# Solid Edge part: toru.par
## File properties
Author: Romil
Template: iso part.par
Last saved by: Romil
Revision: 7
Application: Solid Edge
Accuracy: 0.990
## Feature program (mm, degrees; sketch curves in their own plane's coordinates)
lofted protrusion "unnamed LoftedProtrusion 1"
lofted protrusion "unnamed LoftedProtrusion 2"
lofted protrusion "unnamed LoftedProtrusion 3"
lofted protrusion "unnamed LoftedProtrusion 4"
lofted protrusion "unnamed LoftedProtrusion 5"
lofted protrusion "unnamed LoftedProtrusion 6"
lofted protrusion "unnamed LoftedProtrusion 7"
lofted protrusion "unnamed LoftedProtrusion 8"
lofted protrusion "unnamed LoftedProtrusion 9"
lofted protrusion "unnamed LoftedProtrusion 10"
lofted protrusion "unnamed LoftedProtrusion 11"
lofted protrusion "unnamed LoftedProtrusion 12"
lofted protrusion "unnamed LoftedProtrusion 13"
lofted protrusion "unnamed LoftedProtrusion 14"
lofted protrusion "unnamed LoftedProtrusion 15"
lofted protrusion "unnamed LoftedProtrusion 16"
lofted protrusion "unnamed LoftedProtrusion 17"
lofted protrusion "unnamed LoftedProtrusion 18"
lofted protrusion "unnamed LoftedProtrusion 19"
lofted protrusion "unnamed LoftedProtrusion 20"
lofted protrusion "unnamed LoftedProtrusion 21"
lofted protrusion "unnamed LoftedProtrusion 22"
lofted protrusion "unnamed LoftedProtrusion 23"
lofted protrusion "unnamed LoftedProtrusion 24"
lofted protrusion "unnamed LoftedProtrusion 25"
lofted protrusion "unnamed LoftedProtrusion 26"
lofted protrusion "unnamed LoftedProtrusion 27"
lofted protrusion "unnamed LoftedProtrusion 28"
lofted protrusion "unnamed LoftedProtrusion 29"
lofted protrusion "unnamed LoftedProtrusion 30"
lofted protrusion "unnamed LoftedProtrusion 31"
lofted protrusion "unnamed LoftedProtrusion 32"
lofted protrusion "unnamed LoftedProtrusion 33"
lofted protrusion "unnamed LoftedProtrusion 34"
lofted protrusion "unnamed LoftedProtrusion 35"
lofted protrusion "unnamed LoftedProtrusion 36"
lofted protrusion "unnamed LoftedProtrusion 37"
lofted protrusion "unnamed LoftedProtrusion 38"
lofted protrusion "unnamed LoftedProtrusion 39"
lofted protrusion "unnamed LoftedProtrusion 40"
lofted protrusion "unnamed LoftedProtrusion 41"
lofted protrusion "unnamed LoftedProtrusion 42"
lofted protrusion "unnamed LoftedProtrusion 43"
lofted protrusion "unnamed LoftedProtrusion 44"
lofted protrusion "unnamed LoftedProtrusion 45"
lofted protrusion "unnamed LoftedProtrusion 46"
lofted protrusion "unnamed LoftedProtrusion 47"
lofted protrusion "unnamed LoftedProtrusion 48"
lofted protrusion "unnamed LoftedProtrusion 49"
lofted protrusion "unnamed LoftedProtrusion 50"
lofted protrusion "unnamed LoftedProtrusion 51"
lofted protrusion "unnamed LoftedProtrusion 52"
lofted protrusion "unnamed LoftedProtrusion 53"
lofted protrusion "unnamed LoftedProtrusion 54"
lofted protrusion "unnamed LoftedProtrusion 55"
lofted protrusion "unnamed LoftedProtrusion 56"
lofted protrusion "unnamed LoftedProtrusion 57"
lofted protrusion "unnamed LoftedProtrusion 58"
lofted protrusion "unnamed LoftedProtrusion 59"
lofted protrusion "unnamed LoftedProtrusion 60"
lofted protrusion "unnamed LoftedProtrusion 61"
lofted protrusion "unnamed LoftedProtrusion 62"
lofted protrusion "unnamed LoftedProtrusion 63"
lofted protrusion "unnamed LoftedProtrusion 64"
lofted protrusion "unnamed LoftedProtrusion 65"
lofted protrusion "unnamed LoftedProtrusion 66"
lofted protrusion "unnamed LoftedProtrusion 67"
lofted protrusion "unnamed LoftedProtrusion 68"
lofted protrusion "unnamed LoftedProtrusion 69"
lofted protrusion "unnamed LoftedProtrusion 70"
lofted protrusion "unnamed LoftedProtrusion 71"
lofted protrusion "unnamed LoftedProtrusion 72"
lofted protrusion "unnamed LoftedProtrusion 73"
lofted protrusion "unnamed LoftedProtrusion 74"
lofted protrusion "unnamed LoftedProtrusion 75"
lofted protrusion "unnamed LoftedProtrusion 76"
lofted protrusion "unnamed LoftedProtrusion 77"
lofted protrusion "unnamed LoftedProtrusion 78"
lofted protrusion "unnamed LoftedProtrusion 79"
lofted protrusion "unnamed LoftedProtrusion 80"
lofted protrusion "unnamed LoftedProtrusion 81"
lofted protrusion "unnamed LoftedProtrusion 82"
lofted protrusion "unnamed LoftedProtrusion 83"
lofted protrusion "unnamed LoftedProtrusion 84"
lofted protrusion "unnamed LoftedProtrusion 85"
lofted protrusion "unnamed LoftedProtrusion 86"
lofted protrusion "unnamed LoftedProtrusion 87"
lofted protrusion "unnamed LoftedProtrusion 88"
lofted protrusion "unnamed LoftedProtrusion 89"
lofted protrusion "unnamed LoftedProtrusion 90"
lofted protrusion "unnamed LoftedProtrusion 91"
lofted protrusion "unnamed LoftedProtrusion 92"
lofted protrusion "unnamed LoftedProtrusion 93"
lofted protrusion "unnamed LoftedProtrusion 94"
lofted protrusion "unnamed LoftedProtrusion 95"
lofted protrusion "unnamed LoftedProtrusion 96"
lofted protrusion "unnamed LoftedProtrusion 97"
lofted protrusion "unnamed LoftedProtrusion 98"
lofted protrusion "unnamed LoftedProtrusion 99"
lofted protrusion "unnamed LoftedProtrusion 100"
lofted protrusion "unnamed LoftedProtrusion 101"
lofted protrusion "unnamed LoftedProtrusion 102"
lofted protrusion "unnamed LoftedProtrusion 103"
lofted protrusion "unnamed LoftedProtrusion 104"
lofted protrusion "unnamed LoftedProtrusion 105"
lofted protrusion "unnamed LoftedProtrusion 106"
lofted protrusion "unnamed LoftedProtrusion 107"
lofted protrusion "unnamed LoftedProtrusion 108"
lofted protrusion "unnamed LoftedProtrusion 109"
lofted protrusion "unnamed LoftedProtrusion 110"
lofted protrusion "unnamed LoftedProtrusion 111"
lofted protrusion "unnamed LoftedProtrusion 112"
lofted protrusion "unnamed LoftedProtrusion 113"
lofted protrusion "unnamed LoftedProtrusion 114"
lofted protrusion "unnamed LoftedProtrusion 115"
lofted protrusion "unnamed LoftedProtrusion 116"
lofted protrusion "unnamed LoftedProtrusion 117"
lofted protrusion "unnamed LoftedProtrusion 118"
lofted protrusion "unnamed LoftedProtrusion 119"
lofted protrusion "unnamed LoftedProtrusion 120"
lofted protrusion "unnamed LoftedProtrusion 121"
lofted protrusion "unnamed LoftedProtrusion 122"
lofted protrusion "unnamed LoftedProtrusion 123"
lofted protrusion "unnamed LoftedProtrusion 124"
lofted protrusion "unnamed LoftedProtrusion 125"
lofted protrusion "unnamed LoftedProtrusion 126"
lofted protrusion "unnamed LoftedProtrusion 127"
lofted protrusion "unnamed LoftedProtrusion 128"
lofted protrusion "unnamed LoftedProtrusion 129"
lofted protrusion "unnamed LoftedProtrusion 130"
lofted protrusion "unnamed LoftedProtrusion 131"
lofted protrusion "unnamed LoftedProtrusion 132"
lofted protrusion "unnamed LoftedProtrusion 133"
lofted protrusion "unnamed LoftedProtrusion 134"
lofted protrusion "unnamed LoftedProtrusion 135"
lofted protrusion "unnamed LoftedProtrusion 136"
lofted protrusion "unnamed LoftedProtrusion 137"
lofted protrusion "unnamed LoftedProtrusion 138"
lofted protrusion "unnamed LoftedProtrusion 139"
lofted protrusion "unnamed LoftedProtrusion 140"
lofted protrusion "unnamed LoftedProtrusion 141"
lofted protrusion "unnamed LoftedProtrusion 142"
lofted protrusion "unnamed LoftedProtrusion 143"
lofted protrusion "unnamed LoftedProtrusion 144"
lofted protrusion "unnamed LoftedProtrusion 145"
lofted protrusion "unnamed LoftedProtrusion 146"
lofted protrusion "unnamed LoftedProtrusion 147"
lofted protrusion "unnamed LoftedProtrusion 148"
lofted protrusion "unnamed LoftedProtrusion 149"
lofted protrusion "unnamed LoftedProtrusion 150"
lofted protrusion "unnamed LoftedProtrusion 151"
lofted protrusion "unnamed LoftedProtrusion 152"
lofted protrusion "unnamed LoftedProtrusion 153"
lofted protrusion "unnamed LoftedProtrusion 154"
lofted protrusion "unnamed LoftedProtrusion 155"
lofted protrusion "unnamed LoftedProtrusion 156"
lofted protrusion "unnamed LoftedProtrusion 157"
lofted protrusion "unnamed LoftedProtrusion 158"
lofted protrusion "unnamed LoftedProtrusion 159"
lofted protrusion "unnamed LoftedProtrusion 160"
lofted protrusion "unnamed LoftedProtrusion 161"
lofted protrusion "unnamed LoftedProtrusion 162"
lofted protrusion "unnamed LoftedProtrusion 163"
lofted protrusion "unnamed LoftedProtrusion 164"
lofted protrusion "unnamed LoftedProtrusion 165"
lofted protrusion "unnamed LoftedProtrusion 166"
lofted protrusion "unnamed LoftedProtrusion 167"
lofted protrusion "unnamed LoftedProtrusion 168"
lofted protrusion "unnamed LoftedProtrusion 169"
fillet "Round_1" radius 0.2
fillet "unnamed Round 1"
fillet "unnamed Round 2"
fillet "unnamed Round 3"
fillet "unnamed Round 4"
fillet "unnamed Round 5"
fillet "unnamed Round 6"
fillet "unnamed Round 7"
fillet "unnamed Round 8"
fillet "unnamed Round 9"
fillet "unnamed Round 10"
fillet "unnamed Round 11"
fillet "unnamed Round 12"
fillet "unnamed Round 13"
fillet "unnamed Round 14"
fillet "unnamed Round 15"
fillet "unnamed Round 16"
fillet "unnamed Round 17"
fillet "unnamed Round 18"
fillet "unnamed Round 19"
fillet "unnamed Round 20"
fillet "unnamed Round 21"
fillet "unnamed Round 22"
fillet "unnamed Round 23"
fillet "unnamed Round 24"
fillet "unnamed Round 25"
fillet "unnamed Round 26"
fillet "unnamed Round 27"
fillet "unnamed Round 28"
fillet "unnamed Round 29"
fillet "unnamed Round 30"
fillet "unnamed Round 31"
fillet "unnamed Round 32"
fillet "unnamed Round 33"
fillet "unnamed Round 34"
fillet "unnamed Round 35"
fillet "unnamed Round 36"
fillet "unnamed Round 37"
fillet "unnamed Round 38"
fillet "unnamed Round 39"
fillet "unnamed Round 40"
fillet "unnamed Round 41"
fillet "unnamed Round 42"
fillet "unnamed Round 43"
fillet "unnamed Round 44"
fillet "unnamed Round 45"
fillet "unnamed Round 46"
fillet "unnamed Round 47"
fillet "unnamed Round 48"
fillet "unnamed Round 49"
fillet "unnamed Round 50"
fillet "unnamed Round 51"
fillet "unnamed Round 52"
fillet "unnamed Round 53"
fillet "unnamed Round 54"
fillet "unnamed Round 55"
fillet "unnamed Round 56"
fillet "unnamed Round 57"
fillet "unnamed Round 58"
fillet "unnamed Round 59"
fillet "unnamed Round 60"
fillet "unnamed Round 61"
fillet "unnamed Round 62"
fillet "unnamed Round 63"
fillet "unnamed Round 64"
fillet "unnamed Round 65"
fillet "unnamed Round 66"
fillet "unnamed Round 67"
fillet "unnamed Round 68"
fillet "unnamed Round 69"
fillet "unnamed Round 70"
fillet "unnamed Round 71"
fillet "unnamed Round 72"
fillet "unnamed Round 73"
fillet "unnamed Round 74"
fillet "unnamed Round 75"
fillet "unnamed Round 76"
fillet "unnamed Round 77"
fillet "unnamed Round 78"
fillet "unnamed Round 79"
fillet "unnamed Round 80"
fillet "unnamed Round 81"
fillet "unnamed Round 82"
fillet "unnamed Round 83"
fillet "unnamed Round 84"
fillet "unnamed Round 85"
fillet "unnamed Round 86"
fillet "unnamed Round 87"
fillet "unnamed Round 88"
fillet "unnamed Round 89"
fillet "unnamed Round 90"
fillet "unnamed Round 91"
fillet "unnamed Round 92"
fillet "unnamed Round 93"
fillet "unnamed Round 94"
fillet "unnamed Round 95"
fillet "unnamed Round 96"
fillet "unnamed Round 97"
fillet "unnamed Round 98"
fillet "unnamed Round 99"
fillet "unnamed Round 100"
fillet "unnamed Round 101"
fillet "unnamed Round 102"
fillet "unnamed Round 103"
fillet "unnamed Round 104"
fillet "unnamed Round 105"
fillet "unnamed Round 106"
fillet "unnamed Round 107"
fillet "unnamed Round 108"
fillet "unnamed Round 109"
fillet "unnamed Round 110"
fillet "unnamed Round 111"
fillet "unnamed Round 112"
fillet "unnamed Round 113"
fillet "unnamed Round 114"
fillet "unnamed Round 115"
fillet "unnamed Round 116"
fillet "unnamed Round 117"
fillet "unnamed Round 118"
fillet "unnamed Round 119"
fillet "unnamed Round 120"
fillet "unnamed Round 121"
fillet "unnamed Round 122"
fillet "unnamed Round 123"
fillet "unnamed Round 124"
fillet "unnamed Round 125"
fillet "unnamed Round 126"
fillet "unnamed Round 127"
fillet "unnamed Round 128"
fillet "unnamed Round 129"
fillet "unnamed Round 130"
fillet "unnamed Round 131"
fillet "unnamed Round 132"
fillet "unnamed Round 133"
fillet "unnamed Round 134"
fillet "unnamed Round 135"
fillet "unnamed Round 136"
fillet "unnamed Round 137"
fillet "unnamed Round 138"
fillet "unnamed Round 139"
fillet "unnamed Round 140"
fillet "unnamed Round 141"
fillet "unnamed Round 142"
fillet "unnamed Round 143"
fillet "unnamed Round 144"
fillet "unnamed Round 145"
fillet "unnamed Round 146"
fillet "unnamed Round 147"
fillet "unnamed Round 148"
fillet "unnamed Round 149"
fillet "unnamed Round 150"
fillet "unnamed Round 151"
fillet "unnamed Round 152"
fillet "unnamed Round 153"
fillet "unnamed Round 154"
fillet "unnamed Round 155"
fillet "unnamed Round 156"
fillet "unnamed Round 157"
fillet "unnamed Round 158"
fillet "unnamed Round 159"
fillet "unnamed Round 160"
fillet "unnamed Round 161"
fillet "unnamed Round 162"
fillet "unnamed Round 163"
fillet "unnamed Round 164"
fillet "unnamed Round 165"
fillet "unnamed Round 166"
fillet "unnamed Round 167"
fillet "unnamed Round 168"
swept protrusion "SweptProtrusion_3"
thinwall "Thinwall_1"  Thickness = 0.2 mm
Other named dimensions: "ExtrudedSurface_3": FiniteDepth = 401.058 mm | "Pattern_3": XDirCount = 169; XDirSpacing = 2.2077 mm | "Pattern_4": XDirCount = 169; XDirSpacing = 2.2077 mm
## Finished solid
Body 1: solid body, 1700 faces, 1714 edges, 28 vertices.
  Faces by surface: plane 672, blend 338, offset 299, spline 299, cylinder 92
  Edges by curve: intersection 1526, circle 93, ellipse 92, curve on surface 3
Body 2: sheet body, 12 faces, 37 edges, 26 vertices.
  Faces by surface: cylinder 6, plane 4, swept 2
  Edges by curve: line 21, circle 12, spline 4
Body 3: sheet body, 3 faces, 10 edges, 8 vertices.
  Faces by surface: plane 2, swept 1
  Edges by curve: line 8, spline 2
Bounding box of the edges (mm; curved faces can reach further): 164.379 x 185.157 x 401.058, from (-82.1897, -133.2153, -200.529) to (82.1897, 51.9416, 200.529).
Cylindrical faces by radius (mm): R2.4 x46, R2.6 x46, R11.9186 x2, R28.6968 x2, R30.387 x2
Planar faces by outward normal: +x 1, +y 46, -x 1, -y 46, oblique 578
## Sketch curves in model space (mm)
closed spline through (24.0748, 0, 63.9213), (27.5227, 0, 67.4746), (31.134, 0, 64.111), (27.8672, 0, 60.3874), (24.0919, 0, 63.5717)
ellipse centre (27.4, 0, 64.0217) radii 2.6, 2.6
circle centre (27.4, 0, 64.0246) radius 4.2841
circle centre (27.4, 27, 64.0246) radius 3.55
circle centre (27.4, 25.9, 64.0213) radius 4.2841
circle centre (27.4, 27, 64.0246) radius 4.2841
circle centre (27.4, 28.1, 64.0217) radius 4.2841
circle centre (27.4, 28.1, 64.0217) radius 2.6
circle centre (27.4, 28.1, 64.0217) radius 3.55
line (-27.4, 21.1, 0) -> (-27.4, 28.1, 0)
spline (-27.4, 21.1, 0) -> (-36.5491, -4.2909, 0) -> (-29.7864, -28.3663, 0)
arc centre (-39.022, -35.9, 0) radius 11.9186 from (-27.1034, -35.9, 0) through (-27.7942, -31.9014, 0) to (-29.7864, -28.3663, 0)
line (-27.1034, -37.6254, 0) -> (-27.1034, -35.9, 0)
line (-27.1034, -37.6254, 0) -> (-27.1034, -85.5823, 0)
line (-27.1034, -85.5823, 0) -> (-27.1034, -87.6318, 0)
arc centre (3.2836, -87.6318, 0) radius 30.387 from (-27.1034, -87.6318, 0) through (-27.0189, -89.8967, 0) to (-26.7658, -92.1489, 0)
arc centre (1.2968, -86.1493, 0) radius 28.6968 from (-26.7658, -92.1489, 0) through (-17.2491, -108.048, 0) to (0, -114.8168, 0)
arc centre (-1.2968, -86.1493, 0) radius 28.6968 from (26.7658, -92.1489, 0) through (17.2491, -108.048, 0) to (0, -114.8168, 0)
arc centre (-3.2836, -87.6318, 0) radius 30.387 from (27.1034, -87.6318, 0) through (27.0189, -89.8967, 0) to (26.7658, -92.1489, 0)
line (27.1034, -85.5823, 0) -> (27.1034, -87.6318, 0)
line (27.1034, -37.6254, 0) -> (27.1034, -85.5823, 0)
line (27.1034, -37.6254, 0) -> (27.1034, -35.9, 0)
arc centre (39.022, -35.9, 0) radius 11.9186 from (27.1034, -35.9, 0) through (27.7942, -31.9014, 0) to (29.7864, -28.3663, 0)
spline (27.4, 21.1, 0) -> (36.5491, -4.2909, 0) -> (29.7864, -28.3663, 0)
line (27.4, 21.1, 0) -> (27.4, 28.1, 0)
line (0, -87.8909, 28.9565) -> (0, -133.2153, 28.9565)
line (0, -37.6254, 28.9565) -> (0, -87.8909, 28.9565)
line (0, 28.1, 64.0217) -> (0, 51.9416, 63.8857)
spline (0, 28.1, 64.0217) -> (0, -8.067, 48.6213) -> (0, -37.6254, 28.9565)
circle centre (27.4, 0, 64.0217) radius 3.6217
arc centre (27.1034, 0, 28.9565) radius 3.6 from (29.7442, 0, 26.5098) through (29.4282, 0, 31.7051) to (24.2525, 0, 31.1546)
arc centre (27.1034, 0, 28.9565) radius 3.6 from (29.7123, 0, 26.4758) through (24.7609, 0, 26.2229) to (24.2525, 0, 31.1546)
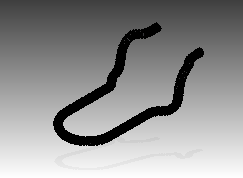
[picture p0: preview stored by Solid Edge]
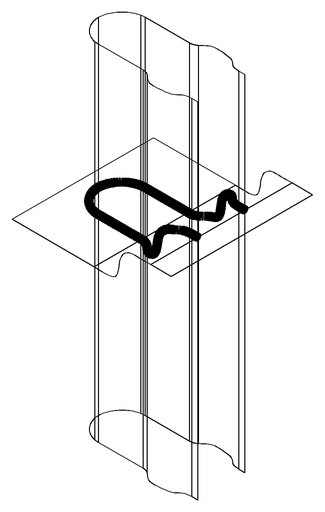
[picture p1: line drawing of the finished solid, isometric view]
